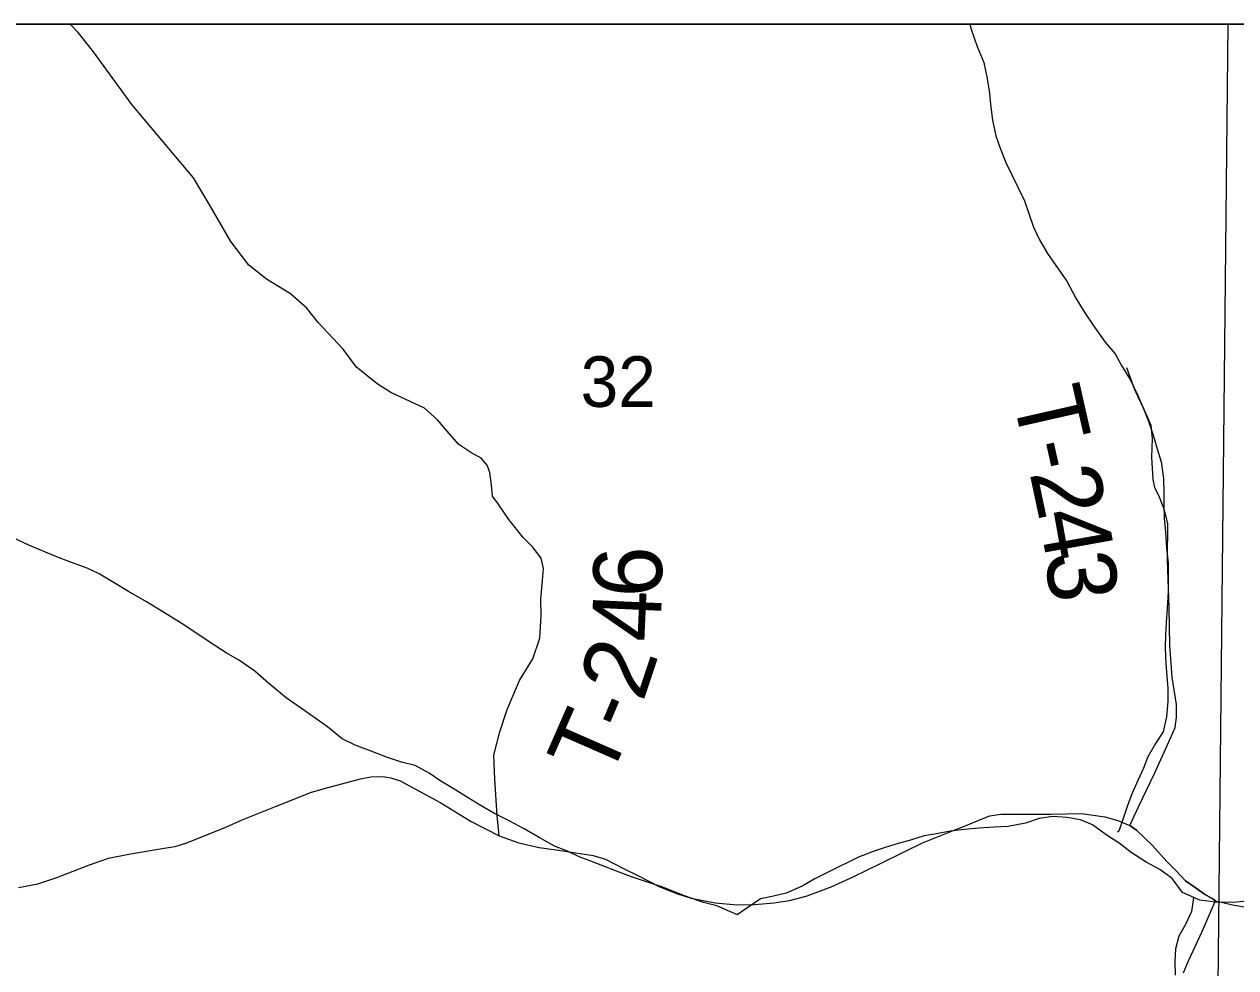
# Model space of a CAD drawing. Extents: x 2.1 to 8.9, y 14.1 to 20.9.
# Drawn here: x 6.478 to 7.48, y 20.12 to 20.9 of the extents above; entities that cross this region are included whole.
import ezdxf

# ---------------------------------------------------------------- set-up
doc = ezdxf.new("R2010")
doc.units = 0
for name, color, linetype in [('Default', 7, 'Continuous'), ('GM_X_City_Street', 7, 'Continuous'), ('GM_X_County_Road_Text', 7, 'Continuous'), ('GM_X_Minor_River_Text', 7, 'Continuous'), ('GM_X_State_Shield', 7, 'Continuous'), ('SH_Cut_Line', 7, 'Continuous'), ('SH_Data', 7, 'Continuous'), ('TX_P_Misc', 7, 'Continuous')]:
    doc.layers.add(name, color=color, linetype=linetype)

msp = doc.modelspace()

# ---------------------------------------------------------------- linework, layer by layer
at = {"layer": 'Default'}
for p, q in [((7.8225, 20.9), (2.1, 20.9)), ((7.4735, 20.9), (6.4715, 20.9)), ((7.4653, 20.105), (7.4735, 20.9))]:
    msp.add_line(p, q, dxfattribs=at)
at = {"layer": 'GM_X_City_Street'}
for p, q in [((6.5226, 20.8933), (6.5158, 20.9)), ((6.5353, 20.8771), (6.5226, 20.8933)), ((6.5462, 20.8621), (6.5353, 20.8771)), ((6.567, 20.8337), (6.5462, 20.8621)), ((6.6178, 20.7731), (6.567, 20.8337)), ((6.6317, 20.7498), (6.6178, 20.7731)), ((6.6487, 20.7204), (6.6317, 20.7498)), ((6.6636, 20.7009), (6.6487, 20.7204)), ((6.6782, 20.6892), (6.6636, 20.7009)), ((6.6982, 20.6772), (6.6782, 20.6892)), ((6.7115, 20.6653), (6.6982, 20.6772)), ((6.7211, 20.6534), (6.7115, 20.6653)), ((6.7416, 20.6313), (6.7211, 20.6534)), ((6.7526, 20.6166), (6.7416, 20.6313)), ((6.7698, 20.6026), (6.7526, 20.6166)), ((7.3964, 20.5977), (7.3897, 20.6159)), ((6.7811, 20.5956), (6.7698, 20.6026)), ((6.8088, 20.5825), (6.7811, 20.5956)), ((7.4041, 20.5814), (7.3964, 20.5977)), ((6.8196, 20.5729), (6.8088, 20.5825)), ((7.4099, 20.5683), (7.4041, 20.5814)), ((6.8292, 20.5615), (6.8196, 20.5729)), ((6.8372, 20.5525), (6.8292, 20.5615)), ((7.411, 20.5574), (7.4099, 20.5683)), ((6.8472, 20.5459), (6.8372, 20.5525)), ((7.4104, 20.542), (7.411, 20.5574)), ((6.8557, 20.5412), (6.8472, 20.5459)), ((6.8608, 20.5354), (6.8557, 20.5412)), ((7.4116, 20.5237), (7.4104, 20.542)), ((6.8629, 20.5295), (6.8608, 20.5354)), ((6.8644, 20.5188), (6.8629, 20.5295)), ((7.413, 20.5171), (7.4116, 20.5237)), ((6.8651, 20.5097), (6.8644, 20.5188)), ((7.4167, 20.5091), (7.413, 20.5171)), ((6.8698, 20.5035), (6.8651, 20.5097)), ((6.8787, 20.4905), (6.8698, 20.5035)), ((7.4207, 20.4991), (7.4167, 20.5091)), ((6.8905, 20.4756), (6.8787, 20.4905)), ((7.4236, 20.4871), (7.4207, 20.4991)), ((7.4233, 20.4573), (7.4236, 20.4871)), ((6.8983, 20.4679), (6.8905, 20.4756)), ((6.9053, 20.4586), (6.8983, 20.4679)), ((6.9073, 20.4501), (6.9053, 20.4586)), ((6.9066, 20.4401), (6.9073, 20.4501)), ((7.4247, 20.4173), (7.4233, 20.4573)), ((6.9052, 20.4246), (6.9066, 20.4401)), ((6.9055, 20.4111), (6.9052, 20.4246)), ((6.9044, 20.3923), (6.9055, 20.4111)), ((7.4253, 20.3867), (7.4247, 20.4173)), ((6.8986, 20.3753), (6.9044, 20.3923)), ((7.4273, 20.3603), (7.4253, 20.3867)), ((6.8876, 20.3573), (6.8986, 20.3753)), ((7.4308, 20.3375), (7.4273, 20.3603)), ((6.8774, 20.3334), (6.8876, 20.3573)), ((6.8711, 20.3151), (6.8774, 20.3334)), ((7.4308, 20.3269), (7.4308, 20.3375)), ((7.4296, 20.3186), (7.4308, 20.3269)), ((6.8662, 20.2956), (6.8711, 20.3151)), ((7.4127, 20.2805), (7.4259, 20.3097)), ((7.4259, 20.3097), (7.4296, 20.3186)), ((6.8671, 20.2758), (6.8662, 20.2956)), ((7.3993, 20.2531), (7.4127, 20.2805)), ((6.8691, 20.2459), (6.8671, 20.2758)), ((7.3921, 20.2376), (7.3993, 20.2531)), ((6.8706, 20.2289), (6.8691, 20.2459)), ((7.3976, 20.2336), (7.3921, 20.2376)), ((7.411, 20.221), (7.3976, 20.2336)), ((7.4227, 20.2079), (7.411, 20.221)), ((7.4302, 20.2002), (7.4227, 20.2079)), ((7.4382, 20.1919), (7.4302, 20.2002)), ((7.4462, 20.1862), (7.4382, 20.1919)), ((7.4539, 20.1807), (7.4462, 20.1862)), ((7.461, 20.1765), (7.4539, 20.1807)), ((7.453, 20.1525), (7.4605, 20.1697)), ((7.4605, 20.1697), (7.463, 20.1753)), ((7.463, 20.1753), (7.461, 20.1765)), ((7.4502, 20.1458), (7.453, 20.1525)), ((7.4426, 20.1297), (7.4483, 20.1417)), ((7.4483, 20.1417), (7.4502, 20.1458)), ((7.4395, 20.1231), (7.4426, 20.1297)), ((7.4367, 20.1157), (7.4395, 20.1231))]:
    msp.add_line(p, q, dxfattribs=at)
at = {"layer": 'GM_X_State_Shield'}
for p, q in [((6.7281, 20.2688), (6.7559, 20.2762)), ((6.7559, 20.2762), (6.7645, 20.2777)), ((6.7645, 20.2777), (6.77, 20.2781)), ((6.77, 20.2781), (6.7761, 20.2778)), ((6.7761, 20.2778), (6.7811, 20.277)), ((6.7811, 20.277), (6.7889, 20.2745)), ((6.7889, 20.2745), (6.8225, 20.2562)), ((6.6857, 20.2532), (6.7154, 20.2651)), ((6.7154, 20.2651), (6.7281, 20.2688)), ((6.6582, 20.2421), (6.6857, 20.2532)), ((6.8225, 20.2562), (6.8476, 20.2408)), ((6.6446, 20.2362), (6.6582, 20.2421)), ((6.8476, 20.2408), (6.8706, 20.2289)), ((7.2568, 20.2375), (7.2686, 20.2426)), ((7.2686, 20.2426), (7.2763, 20.2456)), ((7.2763, 20.2456), (7.2854, 20.247)), ((7.2854, 20.247), (7.3005, 20.2468)), ((7.3005, 20.2468), (7.3268, 20.2468)), ((7.3268, 20.2468), (7.3523, 20.2474)), ((7.3523, 20.2474), (7.3714, 20.2447)), ((7.3714, 20.2447), (7.3824, 20.2417)), ((7.3824, 20.2417), (7.3921, 20.2376)), ((6.6124, 20.2233), (6.6446, 20.2362)), ((7.2318, 20.2277), (7.2401, 20.2309)), ((7.2401, 20.2309), (7.2456, 20.233)), ((7.2456, 20.233), (7.2568, 20.2375)), ((7.3921, 20.2376), (7.3976, 20.2336)), ((7.3976, 20.2336), (7.411, 20.221)), ((6.5935, 20.2187), (6.6028, 20.2202)), ((6.6028, 20.2202), (6.6124, 20.2233)), ((6.8706, 20.2289), (6.8868, 20.2232)), ((6.8868, 20.2232), (6.9038, 20.2194)), ((6.9038, 20.2194), (6.9197, 20.217)), ((7.1877, 20.2069), (7.2207, 20.2231)), ((7.2207, 20.2231), (7.2318, 20.2277)), ((7.411, 20.221), (7.4227, 20.2079)), ((6.5319, 20.205), (6.5475, 20.2104)), ((6.5475, 20.2104), (6.5658, 20.214)), ((6.5658, 20.214), (6.5935, 20.2187)), ((6.9197, 20.217), (6.9484, 20.2127)), ((6.9484, 20.2127), (6.9587, 20.2096)), ((6.9587, 20.2096), (6.9735, 20.2021)), ((6.5048, 20.1945), (6.5319, 20.205)), ((6.9735, 20.2021), (6.9853, 20.1961)), ((7.1628, 20.1948), (7.1877, 20.2069)), ((7.4227, 20.2079), (7.4302, 20.2002)), ((7.4302, 20.2002), (7.4382, 20.1919)), ((6.4732, 20.1864), (6.489, 20.1892)), ((6.489, 20.1892), (6.5048, 20.1945)), ((6.9853, 20.1961), (7.0035, 20.1868)), ((7.1453, 20.1868), (7.1628, 20.1948)), ((7.4382, 20.1919), (7.4462, 20.1862)), ((7.0035, 20.1868), (7.0173, 20.1814)), ((7.0173, 20.1814), (7.0295, 20.1775)), ((7.1107, 20.1755), (7.1254, 20.1793)), ((7.1254, 20.1793), (7.1453, 20.1868)), ((7.4462, 20.1862), (7.4539, 20.1807)), ((7.4539, 20.1807), (7.461, 20.1765)), ((7.0295, 20.1775), (7.0492, 20.1736)), ((7.0492, 20.1736), (7.0675, 20.172)), ((7.0675, 20.172), (7.082, 20.1723)), ((7.082, 20.1723), (7.0979, 20.1735)), ((7.0979, 20.1735), (7.1107, 20.1755)), ((7.461, 20.1765), (7.463, 20.1753)), ((7.463, 20.1753), (7.4784, 20.1716)), ((7.4784, 20.1716), (7.4881, 20.1701))]:
    msp.add_line(p, q, dxfattribs=at)
at = {"layer": 'SH_Cut_Line'}
msp.add_line((7.8225, 20.9), (2.1, 20.9), dxfattribs=at)
at = {"layer": 'SH_Data'}
msp.add_line((2.1, 20.9), (8.9, 20.9), dxfattribs=at)
msp.add_line((2.1, 20.9), (8.9, 20.9), dxfattribs=at)
at = {"layer": 'TX_P_Misc'}
for p, q in [((7.2598, 20.9), (7.261, 20.8959)), ((7.261, 20.8959), (7.2659, 20.8815)), ((7.2659, 20.8815), (7.2716, 20.8684)), ((7.2716, 20.8684), (7.2743, 20.8552)), ((7.2743, 20.8552), (7.2761, 20.843)), ((7.2761, 20.843), (7.2771, 20.8336)), ((7.2771, 20.8336), (7.2786, 20.8207)), ((7.2786, 20.8207), (7.2813, 20.8078)), ((7.2813, 20.8078), (7.2849, 20.7976)), ((7.2849, 20.7976), (7.2898, 20.7856)), ((7.2898, 20.7856), (7.2995, 20.7653)), ((7.2995, 20.7653), (7.3051, 20.7541)), ((7.3051, 20.7541), (7.3088, 20.7435)), ((7.3088, 20.7435), (7.3126, 20.7322)), ((7.3126, 20.7322), (7.3174, 20.7217)), ((7.3174, 20.7217), (7.3242, 20.7105)), ((7.3242, 20.7105), (7.3329, 20.6978)), ((7.3329, 20.6978), (7.34, 20.6877)), ((7.34, 20.6877), (7.3476, 20.6734)), ((7.3476, 20.6734), (7.3544, 20.6622)), ((7.3544, 20.6622), (7.3631, 20.6495)), ((7.3631, 20.6495), (7.3718, 20.6372)), ((7.3718, 20.6372), (7.38, 20.6275)), ((7.38, 20.6275), (7.3852, 20.6178)), ((7.3852, 20.6178), (7.3924, 20.6062)), ((7.3924, 20.6062), (7.3988, 20.5931)), ((7.3988, 20.5931), (7.4037, 20.5814)), ((7.4037, 20.5814), (7.4078, 20.5709)), ((7.4078, 20.5709), (7.4115, 20.5603)), ((7.4115, 20.5603), (7.4149, 20.549)), ((7.4149, 20.549), (7.4182, 20.5381)), ((7.4182, 20.5381), (7.4201, 20.5244)), ((7.4201, 20.5244), (7.4204, 20.5126)), ((7.4204, 20.5126), (7.4203, 20.5031)), ((7.4203, 20.5031), (7.4206, 20.4917)), ((7.4206, 20.4917), (7.4217, 20.48)), ((7.4217, 20.48), (7.4224, 20.4667)), ((6.4817, 20.4692), (6.4686, 20.4753)), ((6.504, 20.46), (6.4817, 20.4692)), ((6.5171, 20.4551), (6.504, 20.46)), ((7.4224, 20.4667), (7.4239, 20.4545)), ((6.5298, 20.4502), (6.5171, 20.4551)), ((6.5398, 20.4455), (6.5298, 20.4502)), ((7.4239, 20.4545), (7.4238, 20.4439)), ((6.5522, 20.4383), (6.5398, 20.4455)), ((7.4238, 20.4439), (7.4238, 20.4306)), ((6.5642, 20.4311), (6.5522, 20.4383)), ((6.579, 20.4224), (6.5642, 20.4311)), ((7.4238, 20.4306), (7.423, 20.4172)), ((6.5925, 20.4141), (6.579, 20.4224)), ((6.6076, 20.4047), (6.5925, 20.4141)), ((7.423, 20.4172), (7.4222, 20.4051)), ((6.6205, 20.3964), (6.6076, 20.4047)), ((7.4222, 20.4051), (7.4217, 20.3952)), ((6.6325, 20.3884), (6.6205, 20.3964)), ((7.4217, 20.3952), (7.4213, 20.3845)), ((6.6449, 20.3804), (6.6325, 20.3884)), ((6.6558, 20.3739), (6.6449, 20.3804)), ((7.4213, 20.3845), (7.422, 20.3716)), ((6.6686, 20.3652), (6.6558, 20.3739)), ((7.422, 20.3716), (7.4227, 20.361)), ((6.6803, 20.3549), (6.6686, 20.3652)), ((7.4227, 20.361), (7.4237, 20.3507)), ((6.6944, 20.3432), (6.6803, 20.3549)), ((7.4237, 20.3507), (7.4236, 20.3401)), ((6.7099, 20.3323), (6.6944, 20.3432)), ((7.4236, 20.3401), (7.4224, 20.3275)), ((6.7286, 20.3192), (6.7099, 20.3323)), ((7.4224, 20.3275), (7.4197, 20.3149)), ((6.7407, 20.3093), (6.7286, 20.3192)), ((7.4197, 20.3149), (7.4135, 20.3052)), ((6.7515, 20.3039), (6.7407, 20.3093)), ((6.7649, 20.299), (6.7515, 20.3039)), ((7.4135, 20.3052), (7.407, 20.2944)), ((6.7784, 20.2937), (6.7649, 20.299)), ((6.7899, 20.2899), (6.7784, 20.2937)), ((6.8011, 20.2872), (6.7899, 20.2899)), ((7.407, 20.2944), (7.4035, 20.2848)), ((6.8127, 20.2807), (6.8011, 20.2872)), ((6.8224, 20.2742), (6.8127, 20.2807)), ((7.4035, 20.2848), (7.3988, 20.2747)), ((6.8325, 20.268), (6.8224, 20.2742)), ((7.3988, 20.2747), (7.3941, 20.2643)), ((6.8437, 20.2612), (6.8325, 20.268)), ((6.8545, 20.2547), (6.8437, 20.2612)), ((7.3941, 20.2643), (7.3902, 20.254)), ((6.8662, 20.2478), (6.8545, 20.2547)), ((7.3902, 20.254), (7.3867, 20.2432)), ((6.8789, 20.2414), (6.8662, 20.2478)), ((6.8913, 20.2349), (6.8789, 20.2414)), ((7.3059, 20.2395), (7.2915, 20.2368)), ((7.3172, 20.2432), (7.3059, 20.2395)), ((7.3285, 20.2451), (7.3172, 20.2432)), ((7.34, 20.2442), (7.3285, 20.2451)), ((7.3514, 20.2423), (7.34, 20.2442)), ((7.3614, 20.238), (7.3514, 20.2423)), ((7.3867, 20.2432), (7.3832, 20.2329)), ((6.9037, 20.2277), (6.8913, 20.2349)), ((7.2324, 20.2307), (7.2222, 20.2289)), ((7.2437, 20.2329), (7.2324, 20.2307)), ((7.2555, 20.2343), (7.2437, 20.2329)), ((7.2672, 20.2354), (7.2555, 20.2343)), ((7.2801, 20.2362), (7.2672, 20.2354)), ((7.2915, 20.2368), (7.2801, 20.2362)), ((7.3727, 20.2299), (7.3614, 20.238)), ((7.3835, 20.223), (7.3727, 20.2299)), ((7.3832, 20.2329), (7.3821, 20.2321)), ((6.9164, 20.2205), (6.9037, 20.2277)), ((6.9272, 20.2163), (6.9164, 20.2205)), ((7.1898, 20.2193), (7.18, 20.2159)), ((7.2007, 20.2226), (7.1898, 20.2193)), ((7.2109, 20.2255), (7.2007, 20.2226)), ((7.2222, 20.2289), (7.2109, 20.2255)), ((7.3932, 20.2153), (7.3835, 20.223)), ((6.9369, 20.2116), (6.9272, 20.2163)), ((6.9465, 20.2081), (6.9369, 20.2116)), ((7.1679, 20.2114), (7.1439, 20.1994)), ((7.18, 20.2159), (7.1679, 20.2114)), ((7.4056, 20.2072), (7.3932, 20.2153)), ((6.9565, 20.2042), (6.9465, 20.2081)), ((6.9677, 20.1997), (6.9565, 20.2042)), ((6.98, 20.1951), (6.9677, 20.1997)), ((7.1439, 20.1994), (7.1316, 20.1933)), ((7.4171, 20.2011), (7.4056, 20.2072)), ((7.4272, 20.1937), (7.4171, 20.2011)), ((6.9957, 20.1899), (6.98, 20.1951)), ((7.0053, 20.1868), (6.9957, 20.1899)), ((7.1316, 20.1933), (7.1211, 20.1874)), ((7.4359, 20.1822), (7.4272, 20.1937)), ((7.0238, 20.1794), (7.0053, 20.1868)), ((7.0396, 20.1738), (7.0238, 20.1794)), ((7.0974, 20.1791), (7.0868, 20.1769)), ((7.1079, 20.1817), (7.0974, 20.1791)), ((7.1211, 20.1874), (7.1079, 20.1817)), ((7.4501, 20.1757), (7.4359, 20.1822)), ((7.0507, 20.1711), (7.0396, 20.1738)), ((7.0677, 20.1637), (7.0507, 20.1711)), ((7.0868, 20.1769), (7.0676, 20.1637)), ((7.445, 20.1781), (7.4432, 20.1664)), ((7.4631, 20.1742), (7.4501, 20.1757)), ((7.4779, 20.1738), (7.4631, 20.1742)), ((7.4889, 20.1749), (7.4779, 20.1738)), ((7.4432, 20.1664), (7.4382, 20.1556)), ((7.4382, 20.1556), (7.4327, 20.146)), ((7.4327, 20.146), (7.43, 20.1356)), ((7.43, 20.1356), (7.4295, 20.125)), ((7.4295, 20.125), (7.4298, 20.1139))]:
    msp.add_line(p, q, dxfattribs=at)

# ---------------------------------------------------------------- texts
at = {"layer": 'GM_X_County_Road_Text'}
msp.add_text('32', height=0.04186, rotation=0, dxfattribs=at).set_placement((6.938, 20.5836))
at = {"layer": 'GM_X_Minor_River_Text'}
for s, rotation, p in [('T', 282.791, (7.2947, 20.5933)), ('-', 282.6219, (7.3041, 20.5519)), ('2', 282.0101, (7.3092, 20.5293)), ('4', 280.1647, (7.3164, 20.4955)), ('6', 89.6501, (7.0052, 20.426)), ('3', 275.6868, (7.3224, 20.4622)), ('4', 87.4152, (7.0035, 20.3887)), ('2', 71.6876, (6.9895, 20.3388)), ('-', 66.8979, (6.9785, 20.3125)), ('T', 66.3073, (6.9612, 20.273))]:
    msp.add_text(s, height=0.0568, rotation=rotation, dxfattribs=at).set_placement(p)

doc.saveas('drawing.dxf')
